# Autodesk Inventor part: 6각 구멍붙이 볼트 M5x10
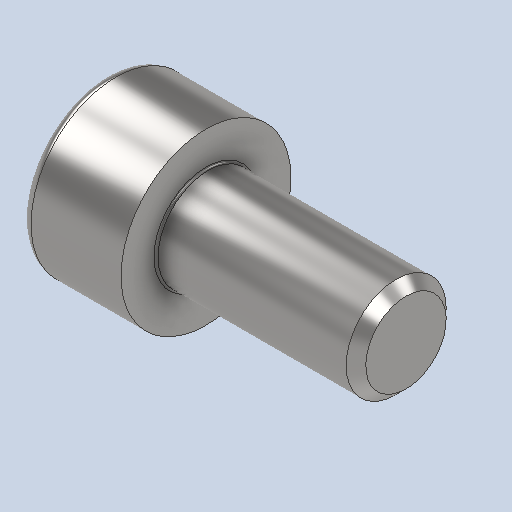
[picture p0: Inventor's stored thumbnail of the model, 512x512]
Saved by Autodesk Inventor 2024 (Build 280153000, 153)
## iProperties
Created: 2026-01
Part Number: 6각 구멍붙이 볼트 M5x10
Material: 강철, 연강
Description: 6각머리 태핑 나사
Document SubType Name: Modeling
Designer: 2-10
Density: 7.85 g/cm^3
Appearance: 기본값
Sending System: Autodesk Inventor 2026
Preprocessor: ST-DEVELOPER v20.1
Author: jhkim
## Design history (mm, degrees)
node "6각 구멍붙이 볼트 M5x101"
node "솔리드1"
body "Solid1"
